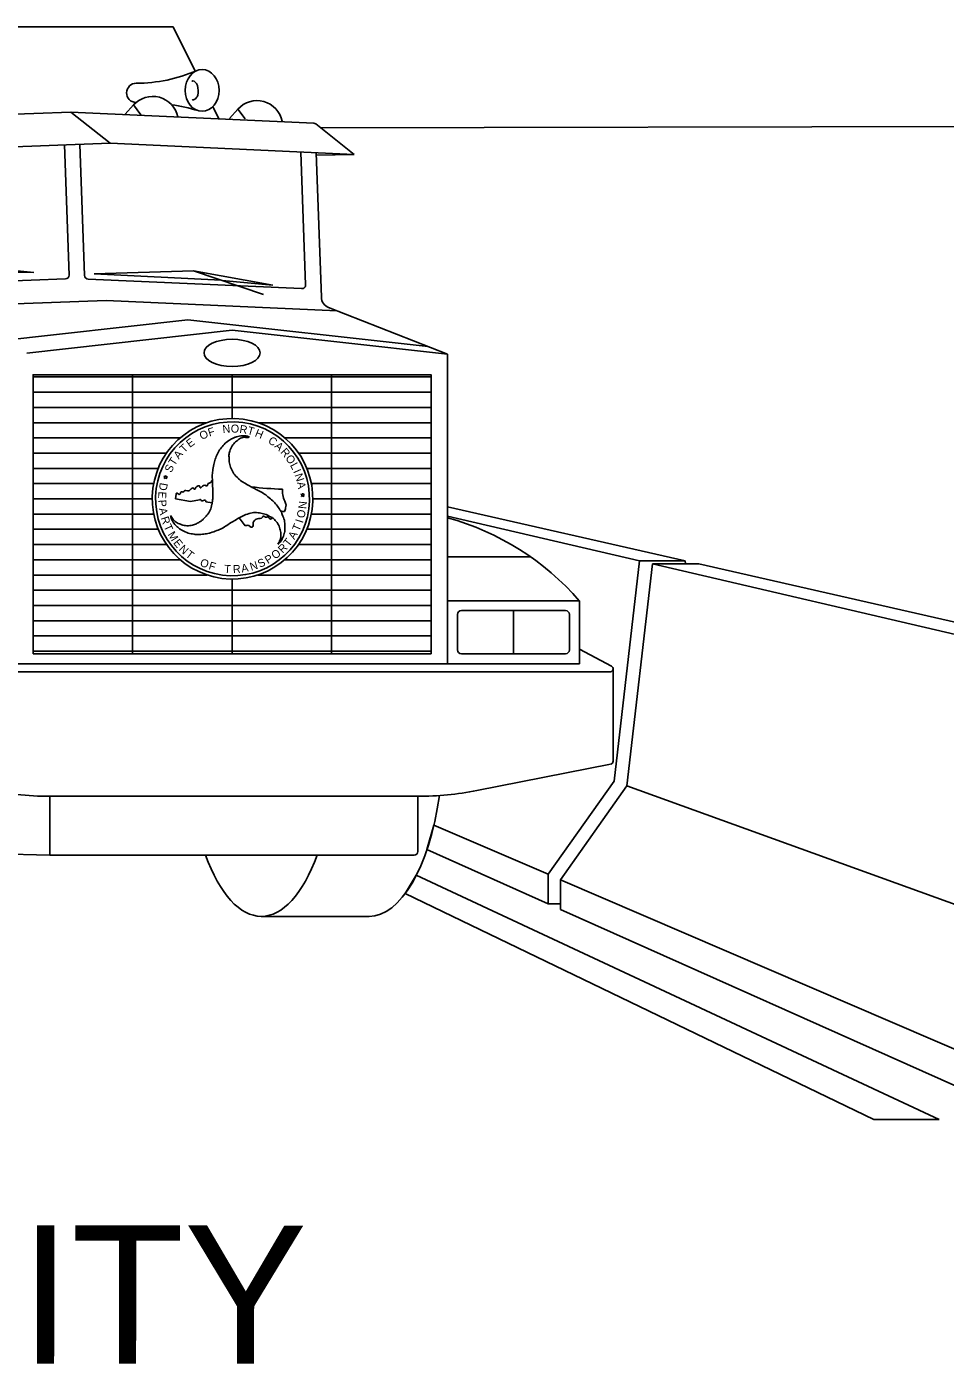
# Model space of a CAD drawing. Extents: x 78728 to 80694, y 10462 to 11664.
# Drawn here: x 79064.2 to 79110.8, y 10615.4 to 10683.2 of the extents above; entities that cross this region are included whole.
import ezdxf

# ---------------------------------------------------------------- set-up
doc = ezdxf.new("R2010")
doc.units = 0
doc.layers.add('Exist Utilities Gas Test Hole SUE LOS A CELL', color=7, linetype='Continuous')

msp = doc.modelspace()

# ---------------------------------------------------------------- linework, layer by layer
at = {"layer": 'Exist Utilities Gas Test Hole SUE LOS A CELL'}
for p, q in [((79037.075, 10683.226), (79071.646, 10683.226)), ((79071.646, 10683.226), (79072.763, 10680.971)), ((79069.634, 10679.265), (79069.212, 10678.793)), ((79069.634, 10679.265), (79070.002, 10678.772)), ((79073.65, 10679.18), (79073.958, 10678.559)), ((79051.124, 10678.34), (79066.464, 10678.897)), ((79068.451, 10677.328), (79066.464, 10678.897)), ((79066.464, 10678.897), (79078.771, 10678.342)), ((79074.92, 10679.049), (79074.498, 10678.577)), ((79074.92, 10679.049), (79075.288, 10678.555)), ((79080.822, 10676.749), (79078.883, 10678.3)), ((79079.119, 10678.112), (79157.26, 10678.243)), ((79053.132, 10676.751), (79068.451, 10677.328)), ((79066.377, 10670.646), (79066.138, 10677.241)), ((79067.15, 10670.63), (79066.909, 10677.27)), ((79068.451, 10677.328), (79080.822, 10676.749)), ((79078.359, 10670.156), (79078.115, 10676.876)), ((79079.155, 10669.518), (79078.889, 10676.839)), ((79078.893, 10676.725), (79080.822, 10676.749)), ((79060.51, 10671.153), (79064.582, 10670.783)), ((79066.191, 10670.446), (79052.394, 10669.945)), ((79064.582, 10670.783), (79061.585, 10670.787)), ((79067.334, 10670.444), (79078.157, 10669.957)), ((79072.67, 10670.866), (79067.64, 10670.704)), ((79067.64, 10670.704), (79074.072, 10670.388)), ((79076.228, 10669.654), (79072.67, 10670.866)), ((79072.67, 10670.866), (79076.693, 10670.137)), ((79076.693, 10670.137), (79074.131, 10670.368)), ((79068.245, 10669.355), (79053.647, 10668.825)), ((79068.245, 10669.355), (79079.96, 10668.828)), ((79085.553, 10666.633), (79079.522, 10669)), ((79061.769, 10667.193), (79072.393, 10668.379)), ((79072.393, 10668.379), (79084.568, 10667.019)), ((79085.553, 10666.633), (79085.553, 10654.145)), ((79069.592, 10665.595), (79069.592, 10651.456)), ((79074.633, 10665.595), (79074.633, 10663.378)), ((79079.675, 10665.595), (79079.675, 10651.456)), ((79084.716, 10665.481), (79064.55, 10665.481)), ((79084.716, 10664.709), (79064.55, 10664.709)), ((79084.716, 10663.937), (79064.55, 10663.937)), ((79073.356, 10663.165), (79064.55, 10663.165)), ((79084.716, 10663.165), (79075.952, 10663.165)), ((79072, 10662.393), (79064.55, 10662.393)), ((79075.506, 10662.447), (79075.498, 10662.44)), ((79075.506, 10662.447), (79075.498, 10662.44)), ((79075.506, 10662.447), (79075.498, 10662.44)), ((79084.716, 10662.393), (79077.308, 10662.393)), ((79071.306, 10661.621), (79064.55, 10661.621)), ((79084.716, 10661.621), (79078.002, 10661.621)), ((79070.888, 10660.85), (79064.55, 10660.85)), ((79084.716, 10660.85), (79078.42, 10660.85)), ((79070.658, 10660.078), (79064.55, 10660.078)), ((79071.221, 10660.394), (79071.17, 10660.444)), ((79071.17, 10660.444), (79071.241, 10660.434)), ((79071.221, 10660.394), (79071.17, 10660.444)), ((79071.17, 10660.444), (79071.241, 10660.434)), ((79071.192, 10660.33), (79071.221, 10660.394)), ((79071.192, 10660.33), (79071.221, 10660.394)), ((79071.251, 10660.365), (79071.192, 10660.33)), ((79071.251, 10660.365), (79071.192, 10660.33)), ((79071.241, 10660.434), (79071.269, 10660.496)), ((79071.241, 10660.434), (79071.269, 10660.496)), ((79071.303, 10660.315), (79071.251, 10660.365)), ((79071.303, 10660.315), (79071.251, 10660.365)), ((79071.269, 10660.496), (79071.284, 10660.428)), ((79071.269, 10660.496), (79071.284, 10660.428)), ((79071.284, 10660.428), (79071.353, 10660.419)), ((79071.284, 10660.428), (79071.353, 10660.419)), ((79071.353, 10660.419), (79071.29, 10660.385)), ((79071.353, 10660.419), (79071.29, 10660.385)), ((79071.29, 10660.385), (79071.303, 10660.315)), ((79071.29, 10660.385), (79071.303, 10660.315)), ((79084.716, 10660.078), (79078.649, 10660.078)), ((79071.761, 10659.308), (79071.802, 10659.549)), ((79071.761, 10659.308), (79071.802, 10659.549)), ((79075.608, 10659.913), (79075.608, 10659.913)), ((79075.608, 10659.913), (79075.608, 10659.913)), ((79078.192, 10659.532), (79078.122, 10659.542)), ((79078.122, 10659.542), (79078.174, 10659.493)), ((79078.192, 10659.532), (79078.122, 10659.542)), ((79078.122, 10659.542), (79078.174, 10659.493)), ((79078.174, 10659.493), (79078.145, 10659.429)), ((79078.174, 10659.493), (79078.145, 10659.429)), ((79078.145, 10659.429), (79078.204, 10659.463)), ((79078.145, 10659.429), (79078.204, 10659.463)), ((79078.222, 10659.594), (79078.192, 10659.532)), ((79078.222, 10659.594), (79078.192, 10659.532)), ((79078.204, 10659.463), (79078.255, 10659.414)), ((79078.204, 10659.463), (79078.255, 10659.414)), ((79078.237, 10659.526), (79078.222, 10659.594)), ((79078.237, 10659.526), (79078.222, 10659.594)), ((79078.306, 10659.52), (79078.237, 10659.526)), ((79078.306, 10659.52), (79078.237, 10659.526)), ((79078.244, 10659.484), (79078.306, 10659.52)), ((79078.244, 10659.484), (79078.306, 10659.52)), ((79078.255, 10659.414), (79078.244, 10659.484)), ((79078.255, 10659.414), (79078.244, 10659.484)), ((79070.585, 10659.306), (79064.55, 10659.306)), ((79072.523, 10659.177), (79071.761, 10659.308)), ((79072.523, 10659.177), (79071.761, 10659.308)), ((79072.978, 10659.248), (79072.523, 10659.177)), ((79072.978, 10659.248), (79072.523, 10659.177)), ((79073.628, 10659.107), (79073.309, 10659.153)), ((79073.628, 10659.107), (79073.309, 10659.153)), ((79078.687, 10658.773), (79078.687, 10658.773)), ((79078.687, 10658.773), (79078.687, 10658.773)), ((79084.716, 10659.306), (79078.723, 10659.306)), ((79085.553, 10658.908), (79097.598, 10656.165)), ((79070.66, 10658.534), (79064.55, 10658.534)), ((79075.287, 10657.933), (79074.997, 10658.345)), ((79074.997, 10658.345), (79074.997, 10658.345)), ((79075.287, 10657.933), (79074.997, 10658.345)), ((79074.997, 10658.345), (79074.997, 10658.345)), ((79084.716, 10658.534), (79078.648, 10658.534)), ((79095.27, 10656.165), (79085.553, 10658.434)), ((79070.89, 10657.762), (79064.55, 10657.762)), ((79084.716, 10657.762), (79078.417, 10657.762)), ((79071.31, 10656.99), (79064.55, 10656.99)), ((79084.716, 10656.99), (79077.998, 10656.99)), ((79072.007, 10656.219), (79064.55, 10656.219)), ((79084.716, 10656.219), (79077.301, 10656.219)), ((79085.553, 10656.36), (79089.77, 10656.36)), ((79095.27, 10656.165), (79093.989, 10645.002)), ((79095.933, 10656.01), (79094.643, 10644.766)), ((79095.27, 10656.165), (79097.598, 10656.165)), ((79095.933, 10656.01), (79098.278, 10656.01)), ((79119.322, 10650.548), (79095.933, 10656.01)), ((79097.598, 10656.165), (79097.615, 10656.01)), ((79098.278, 10656.01), (79119.323, 10651.218)), ((79073.373, 10655.447), (79064.55, 10655.447)), ((79084.716, 10655.447), (79075.935, 10655.447)), ((79084.716, 10654.675), (79064.55, 10654.675)), ((79074.633, 10655.24), (79074.633, 10651.456)), ((79084.716, 10653.903), (79064.55, 10653.903)), ((79086.056, 10651.649), (79086.056, 10653.45)), ((79086.249, 10653.643), (79091.532, 10653.643)), ((79088.89, 10653.643), (79088.89, 10651.456)), ((79091.725, 10653.45), (79091.725, 10651.649)), ((79084.716, 10653.131), (79064.55, 10653.131)), ((79084.716, 10652.359), (79064.55, 10652.359)), ((79084.716, 10651.588), (79064.55, 10651.588)), ((79091.532, 10651.456), (79086.249, 10651.456)), ((79092.228, 10651.686), (79093.858, 10650.826)), ((79063.713, 10650.954), (79085.649, 10650.954)), ((79093.94, 10646.014), (79093.94, 10650.69)), ((79093.815, 10645.862), (79087.033, 10644.525)), ((79093.989, 10645.002), (79090.641, 10640.28)), ((79094.643, 10644.766), (79091.27, 10640.009)), ((79119.312, 10635.851), (79094.643, 10644.766)), ((79065.402, 10644.233), (79065.402, 10641.252)), ((79065.402, 10644.233), (79084.046, 10644.233)), ((79084.046, 10644.233), (79084.046, 10641.445)), ((79084.502, 10641.534), (79084.854, 10642.769)), ((79084.854, 10642.769), (79090.641, 10640.28)), ((79065.402, 10641.252), (79059.605, 10641.403)), ((79065.402, 10641.252), (79083.853, 10641.252)), ((79090.641, 10638.787), (79084.502, 10641.534)), ((79083.965, 10640.231), (79083.402, 10639.303)), ((79110.469, 10627.859), (79083.965, 10640.231)), ((79090.641, 10640.28), (79090.641, 10638.787)), ((79091.27, 10640.009), (79091.27, 10638.506)), ((79091.27, 10640.009), (79119.306, 10627.951)), ((79083.402, 10639.303), (79107.151, 10627.859)), ((79090.641, 10638.787), (79091.27, 10638.787)), ((79091.27, 10638.506), (79115.068, 10627.859)), ((79076.112, 10638.151), (79081.571, 10638.151)), ((79107.151, 10627.859), (79110.469, 10627.859))]:
    msp.add_line(p, q, dxfattribs=at)
for points in [[(79064.227, 10666.69), (79074.633, 10667.853), (79085.553, 10666.633)], [(79093.786, 10650.535), (79056.841, 10650.535)]]:
    msp.add_lwpolyline(points, dxfattribs=at)
for points in [[(79064.55, 10651.456), (79084.716, 10651.456), (79084.716, 10665.595), (79064.55, 10665.595)], [(79092.228, 10650.954), (79085.553, 10650.954), (79085.553, 10654.145), (79092.228, 10654.145)]]:
    msp.add_lwpolyline(points, close=True, dxfattribs=at)
for centre, radius, start, end in [((79069.778, 10688.045), 7.679, 270, 293.39953), ((79069.778, 10679.876), 0.49, 90, 267.70015), ((79070.607, 10678.393), 1.306, 11.73558, 138.14346), ((79070.078, 10669.497), 9.894, 73.36654, 81.33674), ((79075.893, 10678.177), 1.306, 11.73558, 138.14346), ((79078.763, 10678.15), 0.193, 51.33469, 87.42197), ((79066.184, 10670.639), 0.193, 272.07945, 2.07945), ((79067.343, 10670.637), 0.193, 182.07945, 267.42197), ((79078.166, 10670.149), 0.193, 267.42197, 2.07945), ((79079.733, 10669.539), 0.579, 182.07945, 248.57248), ((79074.654, 10659.309), 4.069, 352.42113, 172.42113), ((79074.654, 10659.309), 4.069, 352.42113, 172.42113), ((79074.654, 10659.309), 3.899, 352.42113, 172.42113), ((79074.654, 10659.309), 3.899, 352.42113, 172.42113), ((79078.022, 10681.229), 21.453, 258.09962, 258.19922), ((79078.022, 10681.229), 21.453, 258.09962, 258.19922), ((79074.654, 10659.309), 4.069, 172.42113, 352.42113), ((79074.654, 10659.309), 4.069, 172.42113, 352.42113), ((79074.654, 10659.309), 3.899, 172.42113, 352.42113), ((79074.654, 10659.309), 3.899, 172.42113, 352.42113), ((79078.022, 10681.229), 21.453, 263.53868, 267.74469), ((79078.022, 10681.229), 21.453, 263.53868, 267.74469), ((79081.941, 10645.199), 13.632, 41.01358, 74.63515), ((79086.249, 10653.45), 0.193, 90, 180), ((79091.532, 10653.45), 0.193, 0, 90), ((79086.249, 10651.649), 0.193, 180, 270), ((79091.532, 10651.649), 0.193, 270, 0), ((79093.786, 10650.69), 0.154, 270, 62.18865), ((79093.786, 10646.014), 0.154, 281.15709, 0), ((79065.402, 10659.67), 15.437, 257.50695, 270), ((79084.046, 10659.67), 15.437, 270, 281.15709), ((79083.853, 10641.445), 0.193, 270, 0)]:
    msp.add_arc(centre, radius, start, end, dxfattribs=at)
for centre, major_axis, ratio in [((79073.112, 10680.002), (0, 1.056), 0.8125), ((79074.633, 10666.702), (-1.42, 0), 0.48463)]:
    msp.add_ellipse(centre, major_axis=major_axis, ratio=ratio, dxfattribs=at)
for centre, start_param, end_param in [((79081.571, 10647.498), 3.141593, 4.359994), ((79076.112, 10647.498), 2.302633, 3.980552)]:
    msp.add_ellipse(centre, major_axis=(0, 9.348), ratio=0.407167, start_param=start_param, end_param=end_param, dxfattribs=at)
for points, degree in [([(79072.643, 10680.479), (79072.63, 10680.479), (79072.612, 10680.474), (79072.593, 10680.463)], 2), ([(79072.643, 10680.479), (79072.63, 10680.479), (79072.612, 10680.474), (79072.593, 10680.463)], 2), ([(79072.611, 10679.533), (79072.623, 10679.528), (79072.634, 10679.525), (79072.72, 10679.525), (79072.922, 10679.695), (79072.922, 10680.309), (79072.72, 10680.479), (79072.643, 10680.479)], 3), ([(79072.611, 10679.533), (79072.623, 10679.528), (79072.634, 10679.525), (79072.72, 10679.525), (79072.922, 10679.695), (79072.922, 10680.309), (79072.72, 10680.479), (79072.643, 10680.479)], 3)]:
    msp.add_open_spline(points, degree=degree, dxfattribs=at)
for points in [[(79075.498, 10662.44), (79075.41, 10662.476), (79075.141, 10662.5), (79074.857, 10662.449), (79074.831, 10662.439), (79074.686, 10662.386), (79074.527, 10662.298), (79074.28, 10662.12), (79074.079, 10661.887), (79073.998, 10661.788), (79073.931, 10661.66), (79073.803, 10661.388), (79073.72, 10661.119), (79073.659, 10660.8), (79073.627, 10660.517), (79073.635, 10660.223), (79073.647, 10659.925), (79073.651, 10659.638), (79073.652, 10659.342), (79073.614, 10659.054), (79073.61, 10659.029), (79073.518, 10658.728), (79073.358, 10658.476), (79073.167, 10658.271), (79073.059, 10658.18), (79072.91, 10658.093), (79072.825, 10658.042), (79072.63, 10657.973), (79072.345, 10657.945), (79072.077, 10657.997), (79071.846, 10658.089), (79071.654, 10658.253), (79071.513, 10658.468)], [(79075.498, 10662.44), (79075.41, 10662.476), (79075.141, 10662.5), (79074.857, 10662.449), (79074.831, 10662.439), (79074.686, 10662.386), (79074.527, 10662.298), (79074.28, 10662.12), (79074.079, 10661.887), (79073.998, 10661.788), (79073.931, 10661.66), (79073.803, 10661.388), (79073.72, 10661.119), (79073.659, 10660.8), (79073.627, 10660.517), (79073.635, 10660.223), (79073.647, 10659.925), (79073.651, 10659.638), (79073.652, 10659.342), (79073.614, 10659.054), (79073.61, 10659.029), (79073.518, 10658.728), (79073.358, 10658.476), (79073.167, 10658.271), (79073.059, 10658.18), (79072.91, 10658.093), (79072.825, 10658.042), (79072.63, 10657.973), (79072.345, 10657.945), (79072.077, 10657.997), (79071.846, 10658.089), (79071.654, 10658.253), (79071.513, 10658.468)], [(79076.948, 10657.004), (79077.019, 10657.061), (79077.177, 10657.282), (79077.275, 10657.553), (79077.282, 10657.58), (79077.305, 10657.734), (79077.309, 10657.917), (79077.281, 10658.219), (79077.177, 10658.508), (79077.134, 10658.629), (79077.055, 10658.753), (79076.883, 10658.998), (79076.693, 10659.205), (79076.446, 10659.415), (79076.217, 10659.583), (79075.957, 10659.728), (79075.696, 10659.865), (79075.447, 10660.004), (79075.185, 10660.153), (79074.957, 10660.328), (79074.939, 10660.346), (79074.721, 10660.577), (79074.584, 10660.842), (79074.5, 10661.108), (79074.479, 10661.245), (79074.478, 10661.42), (79074.473, 10661.52), (79074.514, 10661.721), (79074.632, 10661.984), (79074.809, 10662.188), (79075.006, 10662.341), (79075.244, 10662.426), (79075.498, 10662.44), (79075.506, 10662.447)], [(79076.948, 10657.004), (79077.019, 10657.061), (79077.177, 10657.282), (79077.275, 10657.553), (79077.282, 10657.58), (79077.305, 10657.734), (79077.309, 10657.917), (79077.281, 10658.219), (79077.177, 10658.508), (79077.134, 10658.629), (79077.055, 10658.753), (79076.883, 10658.998), (79076.693, 10659.205), (79076.446, 10659.415), (79076.217, 10659.583), (79075.957, 10659.728), (79075.696, 10659.865), (79075.447, 10660.004), (79075.185, 10660.153), (79074.957, 10660.328), (79074.939, 10660.346), (79074.721, 10660.577), (79074.584, 10660.842), (79074.5, 10661.108), (79074.479, 10661.245), (79074.478, 10661.42), (79074.473, 10661.52), (79074.514, 10661.721), (79074.632, 10661.984), (79074.809, 10662.188), (79075.006, 10662.341), (79075.244, 10662.426), (79075.498, 10662.44), (79075.506, 10662.447)], [(79071.802, 10659.549), (79071.797, 10659.573), (79071.841, 10659.594), (79071.948, 10659.532), (79072.012, 10659.574), (79072.016, 10659.623), (79072.068, 10659.666), (79072.144, 10659.64), (79072.226, 10659.72), (79072.293, 10659.727), (79072.429, 10659.709), (79072.612, 10659.85), (79072.682, 10659.851), (79072.693, 10659.805), (79072.733, 10659.791), (79072.82, 10659.916), (79072.841, 10659.933), (79072.974, 10659.966), (79073.005, 10659.938), (79073.006, 10659.877), (79073.023, 10659.862), (79073.068, 10659.887), (79073.134, 10659.951), (79073.245, 10659.991), (79073.362, 10659.961), (79073.395, 10660.055), (79073.546, 10660.13), (79073.582, 10660.182), (79073.597, 10660.239)], [(79071.802, 10659.549), (79071.797, 10659.573), (79071.841, 10659.594), (79071.948, 10659.532), (79072.012, 10659.574), (79072.016, 10659.623), (79072.068, 10659.666), (79072.144, 10659.64), (79072.226, 10659.72), (79072.293, 10659.727), (79072.429, 10659.709), (79072.612, 10659.85), (79072.682, 10659.851), (79072.693, 10659.805), (79072.733, 10659.791), (79072.82, 10659.916), (79072.841, 10659.933), (79072.974, 10659.966), (79073.005, 10659.938), (79073.006, 10659.877), (79073.023, 10659.862), (79073.068, 10659.887), (79073.134, 10659.951), (79073.245, 10659.991), (79073.362, 10659.961), (79073.395, 10660.055), (79073.546, 10660.13), (79073.582, 10660.182), (79073.597, 10660.239)], [(79073.635, 10660.23), (79073.635, 10660.223), (79073.647, 10659.925), (79073.651, 10659.638), (79073.652, 10659.342), (79073.626, 10659.107)], [(79073.635, 10660.23), (79073.635, 10660.223), (79073.647, 10659.925), (79073.651, 10659.638), (79073.652, 10659.342), (79073.626, 10659.107)], [(79077.109, 10658.676), (79077.055, 10658.753), (79076.883, 10658.998), (79076.693, 10659.205), (79076.446, 10659.415), (79076.217, 10659.583), (79075.957, 10659.728), (79075.696, 10659.865), (79075.608, 10659.913)], [(79077.109, 10658.676), (79077.055, 10658.753), (79076.883, 10658.998), (79076.693, 10659.205), (79076.446, 10659.415), (79076.217, 10659.583), (79075.957, 10659.728), (79075.696, 10659.865), (79075.608, 10659.913)], [(79077.178, 10659.793), (79077.199, 10659.516), (79077.298, 10659.18), (79077.366, 10658.995), (79077.344, 10658.846), (79077.285, 10658.672), (79077.111, 10658.677)], [(79077.178, 10659.793), (79077.199, 10659.516), (79077.298, 10659.18), (79077.366, 10658.995), (79077.344, 10658.846), (79077.285, 10658.672), (79077.111, 10658.677)], [(79073.309, 10659.153), (79073.286, 10659.216), (79073.226, 10659.242), (79073.136, 10659.209), (79073.073, 10659.221), (79073.011, 10659.28), (79072.978, 10659.248)], [(79073.309, 10659.153), (79073.286, 10659.216), (79073.226, 10659.242), (79073.136, 10659.209), (79073.073, 10659.221), (79073.011, 10659.28), (79072.978, 10659.248)], [(79071.513, 10658.468), (79071.53, 10658.374), (79071.642, 10658.128), (79071.827, 10657.906), (79071.848, 10657.891), (79071.969, 10657.788), (79072.125, 10657.697), (79072.402, 10657.57), (79072.702, 10657.516), (79072.829, 10657.493), (79072.979, 10657.499), (79073.273, 10657.526), (79073.546, 10657.586), (79073.855, 10657.694), (79074.113, 10657.807), (79074.367, 10657.962), (79074.617, 10658.122), (79074.865, 10658.268), (79075.122, 10658.415), (79075.389, 10658.529), (79075.418, 10658.536), (79075.724, 10658.608), (79076.02, 10658.595), (79076.289, 10658.535), (79076.427, 10658.486), (79076.572, 10658.397), (79076.665, 10658.352), (79076.818, 10658.216), (79076.983, 10657.984), (79077.073, 10657.729), (79077.108, 10657.479), (79077.063, 10657.231), (79076.948, 10657.004)], [(79071.513, 10658.468), (79071.53, 10658.374), (79071.642, 10658.128), (79071.827, 10657.906), (79071.848, 10657.891), (79071.969, 10657.788), (79072.125, 10657.697), (79072.402, 10657.57), (79072.702, 10657.516), (79072.829, 10657.493), (79072.979, 10657.499), (79073.273, 10657.526), (79073.546, 10657.586), (79073.855, 10657.694), (79074.113, 10657.807), (79074.367, 10657.962), (79074.617, 10658.122), (79074.865, 10658.268), (79075.122, 10658.415), (79075.389, 10658.529), (79075.418, 10658.536), (79075.724, 10658.608), (79076.02, 10658.595), (79076.289, 10658.535), (79076.427, 10658.486), (79076.572, 10658.397), (79076.665, 10658.352), (79076.818, 10658.216), (79076.983, 10657.984), (79077.073, 10657.729), (79077.108, 10657.479), (79077.063, 10657.231), (79076.948, 10657.004)], [(79074.997, 10658.345), (79075.122, 10658.415), (79075.389, 10658.529), (79075.418, 10658.536), (79075.724, 10658.608), (79076.02, 10658.595), (79076.289, 10658.535), (79076.427, 10658.486), (79076.572, 10658.397), (79076.658, 10658.354)], [(79074.997, 10658.345), (79075.122, 10658.415), (79075.389, 10658.529), (79075.418, 10658.536), (79075.724, 10658.608), (79076.02, 10658.595), (79076.289, 10658.535), (79076.427, 10658.486), (79076.572, 10658.397), (79076.658, 10658.354)], [(79076.657, 10658.353), (79076.61, 10658.288), (79076.548, 10658.291), (79076.453, 10658.39), (79076.32, 10658.381), (79076.264, 10658.424), (79076.225, 10658.43), (79076.115, 10658.324), (79075.982, 10658.313), (79075.752, 10658.187), (79075.697, 10658.103), (79075.687, 10657.907), (79075.631, 10657.875), (79075.57, 10657.893), (79075.447, 10657.961), (79075.287, 10657.933)], [(79076.657, 10658.353), (79076.61, 10658.288), (79076.548, 10658.291), (79076.453, 10658.39), (79076.32, 10658.381), (79076.264, 10658.424), (79076.225, 10658.43), (79076.115, 10658.324), (79075.982, 10658.313), (79075.752, 10658.187), (79075.697, 10658.103), (79075.687, 10657.907), (79075.631, 10657.875), (79075.57, 10657.893), (79075.447, 10657.961), (79075.287, 10657.933)]]:
    msp.add_spline(points, degree=3, dxfattribs=at)

# ---------------------------------------------------------------- texts
for s, height, rotation, p in [('F', 0.407, 17.49185, (79073.48, 10662.459)), ('N', 0.406, 5.40491, (79074.164, 10662.634)), ('O', 0.407, 357.9068, (79074.559, 10662.669)), ('R', 0.406, 351.29687, (79074.988, 10662.654)), ('T', 0.407, 344.64724, (79075.372, 10662.595)), ('H', 0.405, 337.56252, (79075.754, 10662.487)), ('T', 0.405, 43.6937, (79072.203, 10661.609)), ('E', 0.404, 36.57807, (79072.491, 10661.882)), ('O', 0.406, 24.63869, (79073.089, 10662.282)), ('C', 0.405, 325.22017, (79076.418, 10662.172)), ('A', 0.405, 317.72314, (79076.749, 10661.94)), ('T', 0.407, 57.80123, (79071.721, 10660.952)), ('A', 0.407, 50.74892, (79071.937, 10661.284)), ('R', 0.405, 311.35919, (79077.058, 10661.66)), ('O', 0.406, 304.23959, (79077.313, 10661.368)), ('S', 0.405, 64.17738, (79071.552, 10660.604)), ('L', 0.405, 298.00591, (79077.556, 10661.011)), ('I', 0.406, 294.01657, (79077.714, 10660.698)), ('D', 0.406, 260.27413, (79070.98, 10660.145)), ('N', 0.406, 288.31647, (79077.792, 10660.516)), ('A', 0.406, 280.88449, (79077.915, 10660.137)), ('E', 0.404, 266.56202, (79070.905, 10659.686)), ('P', 0.406, 274.09441, (79070.887, 10659.245)), ('A', 0.405, 280.68699, (79070.918, 10658.813)), ('O', 0.404, 77.38125, (79078.287, 10658.299)), ('N', 0.406, 84.62926, (79078.39, 10658.779)), ('R', 0.406, 287.75562, (79071.012, 10658.342)), ('T', 0.405, 294.40616, (79071.153, 10657.916)), ('T', 0.405, 66.59571, (79078.03, 10657.629)), ('I', 0.407, 72.24562, (79078.21, 10658.051)), ('M', 0.405, 301.6412, (79071.349, 10657.5)), ('A', 0.407, 59.51129, (79077.791, 10657.212)), ('E', 0.405, 309.10797, (79071.627, 10657.065)), ('N', 0.406, 316.07951, (79071.907, 10656.728)), ('T', 0.405, 322.92151, (79072.24, 10656.414)), ('O', 0.407, 38.13535, (79076.814, 10656.219)), ('R', 0.406, 45.32446, (79077.198, 10656.525)), ('T', 0.404, 51.42425, (79077.51, 10656.848)), ('O', 0.405, 336.2252, (79072.964, 10655.939)), ('F', 0.405, 343.39043, (79073.416, 10655.748)), ('A', 0.404, 10.00941, (79075.13, 10655.57)), ('N', 0.404, 17.04104, (79075.601, 10655.66)), ('S', 0.404, 24.25151, (79076.037, 10655.803)), ('P', 0.406, 31.44336, (79076.445, 10655.99)), ('T', 0.404, 356.29966, (79074.224, 10655.562)), ('R', 0.406, 3.25628, (79074.683, 10655.538)), ('WORK ZONE SAFETY & MOBILITY', 7.00003, 359.9598, (78926.572, 10615.59))]:
    msp.add_text(s, height=height, rotation=rotation, dxfattribs=at).set_placement(p)

doc.saveas('drawing.dxf')
